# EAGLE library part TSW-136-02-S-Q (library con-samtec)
THROUGH-HOLE .025" SQ POST HEADER Source: Samtec TSW.pdf
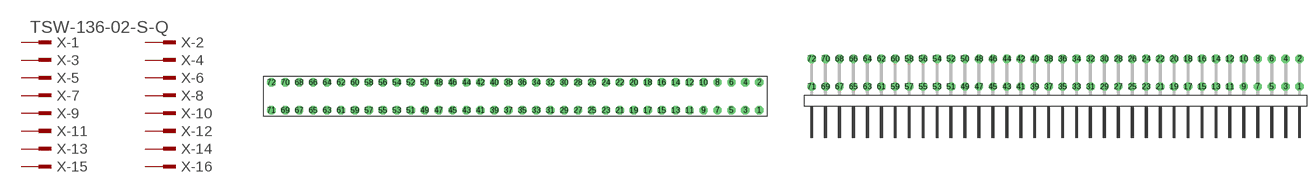
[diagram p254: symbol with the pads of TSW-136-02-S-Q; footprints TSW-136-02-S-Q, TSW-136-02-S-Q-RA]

Designator prefix X; gates -1=MPINV -2=MPIN -3=MPIN -4=MPIN -5=MPIN -6=MPIN -7=MPIN -8=MPIN -9=MPIN -10=MPIN -11=MPIN -12=MPIN -13=MPIN -14=MPIN -15=MPIN -16=MPIN -17=MPIN -18=MPIN -19=MPIN -20=MPIN -21=MPIN -22=MPIN -23=MPIN -24=MPIN -25=MPIN -26=MPIN -27=MPIN -28=MPIN -29=MPIN -30=MPIN -31=MPIN -32=MPIN -33=MPIN -34=MPIN -35=MPIN -36=MPIN -37=MPIN -38=MPIN -39=MPIN -40=MPIN -41=MPIN -42=MPIN -43=MPIN -44=MPIN -45=MPIN -46=MPIN -47=MPIN -48=MPIN -49=MPIN -50=MPIN -51=MPIN -52=MPIN -53=MPIN -54=MPIN -55=MPIN -56=MPIN -57=MPIN -58=MPIN -59=MPIN -60=MPIN -61=MPIN -62=MPIN -63=MPIN -64=MPIN -65=MPIN -66=MPIN -67=MPIN -68=MPIN -69=MPIN -70=MPIN -71=MPIN -72=MPIN

## TSW-136-02-S-Q (OC_FARNELL: unknown; OC_NEWARK: unknown)  [TSW-136-02-S-Q]
1  -1:1  pas
2  -2:1  pas
3  -3:1  pas
4  -4:1  pas
5  -5:1  pas
6  -6:1  pas
7  -7:1  pas
8  -8:1  pas
9  -9:1  pas
10  -10:1  pas
11  -11:1  pas
12  -12:1  pas
13  -13:1  pas
14  -14:1  pas
15  -15:1  pas
16  -16:1  pas
17  -17:1  pas
18  -18:1  pas
19  -19:1  pas
20  -20:1  pas
21  -21:1  pas
22  -22:1  pas
23  -23:1  pas
24  -24:1  pas
25  -25:1  pas
26  -26:1  pas
27  -27:1  pas
28  -28:1  pas
29  -29:1  pas
30  -30:1  pas
31  -31:1  pas
32  -32:1  pas
33  -33:1  pas
34  -34:1  pas
35  -35:1  pas
36  -36:1  pas
37  -37:1  pas
38  -38:1  pas
39  -39:1  pas
40  -40:1  pas
41  -41:1  pas
42  -42:1  pas
43  -43:1  pas
44  -44:1  pas
45  -45:1  pas
46  -46:1  pas
47  -47:1  pas
48  -48:1  pas
49  -49:1  pas
50  -50:1  pas
51  -51:1  pas
52  -52:1  pas
53  -53:1  pas
54  -54:1  pas
55  -55:1  pas
56  -56:1  pas
57  -57:1  pas
58  -58:1  pas
59  -59:1  pas
60  -60:1  pas
61  -61:1  pas
62  -62:1  pas
63  -63:1  pas
64  -64:1  pas
65  -65:1  pas
66  -66:1  pas
67  -67:1  pas
68  -68:1  pas
69  -69:1  pas
70  -70:1  pas
71  -71:1  pas
72  -72:1  pas

## TSW-136-02-S-Q-RA (OC_FARNELL: unknown; OC_NEWARK: unknown)  [TSW-136-02-S-Q-RA]
Pads as for TSW-136-02-S-Q

## Footprint TSW-136-02-S-Q (pad centres in mm)
THROUGH-HOLE .025" SQ POST HEADER Source: Samtec TSW.pdf
drill 1 pad 1.5 octagon: 1 44.45,-2.54; 2 44.45,2.54; 3 41.91,-2.54; 4 41.91,2.54; 5 39.37,-2.54; 6 39.37,2.54; 7 36.83,-2.54; 8 36.83,2.54; 9 34.29,-2.54; 10 34.29,2.54; 11 31.75,-2.54; 12 31.75,2.54; 13 29.21,-2.54; 14 29.21,2.54; 15 26.67,-2.54; 16 26.67,2.54; 17 24.13,-2.54; 18 24.13,2.54; 19 21.59,-2.54; 20 21.59,2.54; 21 19.05,-2.54; 22 19.05,2.54; 23 16.51,-2.54; 24 16.51,2.54; 25 13.97,-2.54; 26 13.97,2.54; 27 11.43,-2.54; 28 11.43,2.54; 29 8.89,-2.54; 30 8.89,2.54; 31 6.35,-2.54; 32 6.35,2.54; 33 3.81,-2.54; 34 3.81,2.54; 35 1.27,-2.54; 36 1.27,2.54; 37 -1.27,-2.54; 38 -1.27,2.54; 39 -3.81,-2.54; 40 -3.81,2.54; 41 -6.35,-2.54; 42 -6.35,2.54; 43 -8.89,-2.54; 44 -8.89,2.54; 45 -11.43,-2.54; 46 -11.43,2.54; 47 -13.97,-2.54; 48 -13.97,2.54; 49 -16.51,-2.54; 50 -16.51,2.54; 51 -19.05,-2.54; 52 -19.05,2.54; 53 -21.59,-2.54; 54 -21.59,2.54; 55 -24.13,-2.54; 56 -24.13,2.54; 57 -26.67,-2.54; 58 -26.67,2.54; 59 -29.21,-2.54; 60 -29.21,2.54; 61 -31.75,-2.54; 62 -31.75,2.54; 63 -34.29,-2.54; 64 -34.29,2.54; 65 -36.83,-2.54; 66 -36.83,2.54; 67 -39.37,-2.54; 68 -39.37,2.54; 69 -41.91,-2.54; 70 -41.91,2.54; 71 -44.45,-2.54; 72 -44.45,2.54

## Footprint TSW-136-02-S-Q-RA (pad centres in mm)
THROUGH-HOLE .025" SQ POST HEADER Source: Samtec TSW.pdf
drill 1 pad 1.5 octagon: 1 44.45,1.524; 2 44.45,6.604; 3 41.91,1.524; 4 41.91,6.604; 5 39.37,1.524; 6 39.37,6.604; 7 36.83,1.524; 8 36.83,6.604; 9 34.29,1.524; 10 34.29,6.604; 11 31.75,1.524; 12 31.75,6.604; 13 29.21,1.524; 14 29.21,6.604; 15 26.67,1.524; 16 26.67,6.604; 17 24.13,1.524; 18 24.13,6.604; 19 21.59,1.524; 20 21.59,6.604; 21 19.05,1.524; 22 19.05,6.604; 23 16.51,1.524; 24 16.51,6.604; 25 13.97,1.524; 26 13.97,6.604; 27 11.43,1.524; 28 11.43,6.604; 29 8.89,1.524; 30 8.89,6.604; 31 6.35,1.524; 32 6.35,6.604; 33 3.81,1.524; 34 3.81,6.604; 35 1.27,1.524; 36 1.27,6.604; 37 -1.27,1.524; 38 -1.27,6.604; 39 -3.81,1.524; 40 -3.81,6.604; 41 -6.35,1.524; 42 -6.35,6.604; 43 -8.89,1.524; 44 -8.89,6.604; 45 -11.43,1.524; 46 -11.43,6.604; 47 -13.97,1.524; 48 -13.97,6.604; 49 -16.51,1.524; 50 -16.51,6.604; 51 -19.05,1.524; 52 -19.05,6.604; 53 -21.59,1.524; 54 -21.59,6.604; 55 -24.13,1.524; 56 -24.13,6.604; 57 -26.67,1.524; 58 -26.67,6.604; 59 -29.21,1.524; 60 -29.21,6.604; 61 -31.75,1.524; 62 -31.75,6.604; 63 -34.29,1.524; 64 -34.29,6.604; 65 -36.83,1.524; 66 -36.83,6.604; 67 -39.37,1.524; 68 -39.37,6.604; 69 -41.91,1.524; 70 -41.91,6.604; 71 -44.45,1.524; 72 -44.45,6.604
